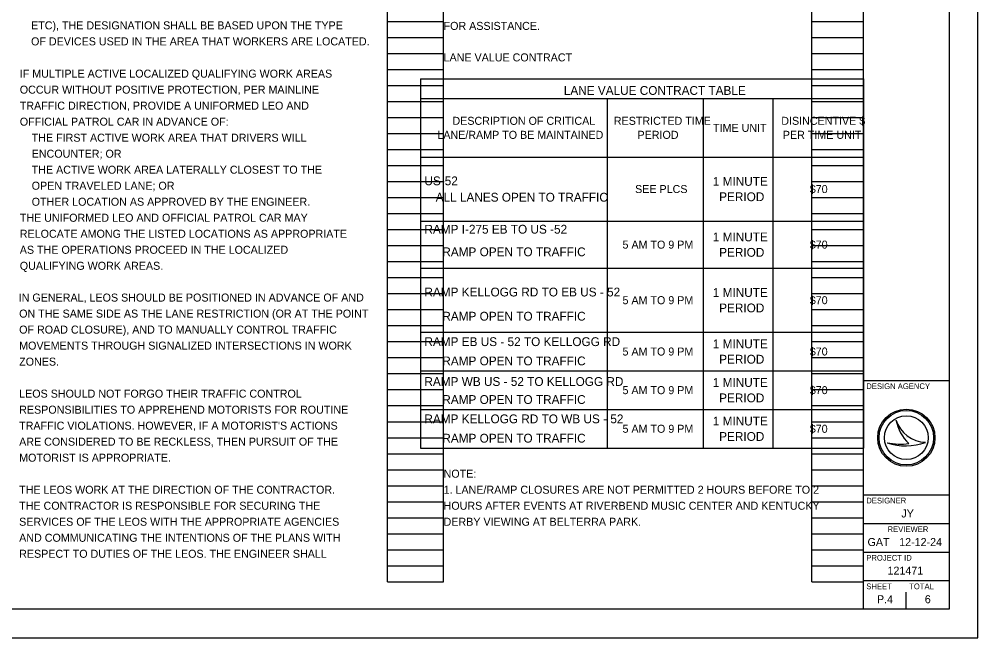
# Model space of a CAD drawing. Extents: x -40 to 107, y -47 to 37.
# Drawn here: x 17.24 to 34, y 0 to 10.82 of the extents above; entities that cross this region are included whole.
import ezdxf

# ---------------------------------------------------------------- set-up
doc = ezdxf.new("R2010")
doc.units = 0
for name, color, linetype in [('Default', 7, 'Continuous'), ('SH_Border', 7, 'Continuous'), ('SH_Cut_Line', 7, 'Continuous'), ('SH_Data', 7, 'Continuous'), ('SH_Text', 7, 'Continuous')]:
    doc.layers.add(name, color=color, linetype=linetype)

msp = doc.modelspace()

# ---------------------------------------------------------------- linework, layer by layer
at = {"layer": 'Default'}
for p, q in [((24.259, 9.775), (32, 9.775)), ((24.259, 9.775), (24.259, 3.318)), ((32, 9.775), (32, 3.318)), ((24.259, 9.429), (27.52, 9.429)), ((27.52, 9.429), (32, 9.429)), ((27.52, 9.429), (27.52, 3.318)), ((29.2, 9.429), (29.2, 3.318)), ((30.419, 9.429), (30.419, 3.318)), ((24.259, 8.408), (32, 8.408)), ((24.259, 7.288), (32, 7.288)), ((24.259, 6.464), (32, 6.464)), ((24.259, 5.344), (32, 5.344)), ((24.259, 4.669), (32, 4.669)), ((24.259, 3.994), (32, 3.994)), ((24.259, 3.318), (32, 3.318))]:
    msp.add_line(p, q, dxfattribs=at)
at = {"layer": 'SH_Border'}
for p, q in [((32, 0.5), (32, 21.5)), ((32, 4.5), (33.5, 4.5)), ((32, 2.5), (33.5, 2.5)), ((32, 2), (33.5, 2)), ((32, 1.5), (33.5, 1.5)), ((32, 1), (33.5, 1))]:
    msp.add_line(p, q, dxfattribs=at)
msp.add_lwpolyline([(1.5, 21.5), (33.5, 21.5), (33.5, 0.5), (1.5, 0.5)], close=True, dxfattribs=at)
at = {"layer": 'SH_Cut_Line'}
msp.add_lwpolyline([(0, 0), (34, 0), (34, 22), (0, 22)], close=True, dxfattribs=at)
at = {"layer": 'SH_Data'}
for p, q in [((23.68, 0.98), (23.68, 21.14)), ((24.66, 0.98), (24.66, 21.14)), ((31.1, 0.98), (31.1, 21.14)), ((32, 0.98), (32, 21.14)), ((23.68, 10.78), (24.66, 10.78)), ((31.1, 10.78), (32, 10.78)), ((23.68, 10.5), (24.66, 10.5)), ((31.1, 10.5), (32, 10.5)), ((23.68, 10.22), (24.66, 10.22)), ((31.1, 10.22), (32, 10.22)), ((23.68, 9.94), (24.66, 9.94)), ((31.1, 9.94), (32, 9.94)), ((23.68, 9.66), (24.66, 9.66)), ((31.1, 9.66), (32, 9.66)), ((23.68, 9.38), (24.66, 9.38)), ((31.1, 9.38), (32, 9.38)), ((23.68, 9.1), (24.66, 9.1)), ((31.1, 9.1), (32, 9.1)), ((23.68, 8.82), (24.66, 8.82)), ((31.1, 8.82), (32, 8.82)), ((23.68, 8.54), (24.66, 8.54)), ((31.1, 8.54), (32, 8.54)), ((23.68, 8.26), (24.66, 8.26)), ((31.1, 8.26), (32, 8.26)), ((23.68, 7.98), (24.66, 7.98)), ((31.1, 7.98), (32, 7.98)), ((23.68, 7.7), (24.66, 7.7)), ((31.1, 7.7), (32, 7.7)), ((23.68, 7.42), (24.66, 7.42)), ((31.1, 7.42), (32, 7.42)), ((23.68, 7.14), (24.66, 7.14)), ((31.1, 7.14), (32, 7.14)), ((23.68, 6.86), (24.66, 6.86)), ((31.1, 6.86), (32, 6.86)), ((23.68, 6.58), (24.66, 6.58)), ((31.1, 6.58), (32, 6.58)), ((23.68, 6.3), (24.66, 6.3)), ((31.1, 6.3), (32, 6.3)), ((23.68, 6.02), (24.66, 6.02)), ((31.1, 6.02), (32, 6.02)), ((23.68, 5.74), (24.66, 5.74)), ((31.1, 5.74), (32, 5.74)), ((23.68, 5.46), (24.66, 5.46)), ((31.1, 5.46), (32, 5.46)), ((23.68, 5.18), (24.66, 5.18)), ((31.1, 5.18), (32, 5.18)), ((23.68, 4.9), (24.66, 4.9)), ((31.1, 4.9), (32, 4.9)), ((23.68, 4.62), (24.66, 4.62)), ((31.1, 4.62), (32, 4.62)), ((23.68, 4.34), (24.66, 4.34)), ((31.1, 4.34), (32, 4.34)), ((23.68, 4.06), (24.66, 4.06)), ((31.1, 4.06), (32, 4.06)), ((23.68, 3.78), (24.66, 3.78)), ((31.1, 3.78), (32, 3.78)), ((32.567, 3.81), (32.567, 3.81)), ((23.68, 3.5), (24.66, 3.5)), ((31.1, 3.5), (32, 3.5)), ((32.417, 3.41), (32.417, 3.41)), ((32.75, 3.5), (32.75, 3.5)), ((33.087, 3.419), (33.087, 3.419)), ((23.68, 3.22), (24.66, 3.22)), ((31.1, 3.22), (32, 3.22)), ((23.68, 2.94), (24.66, 2.94)), ((31.1, 2.94), (32, 2.94)), ((23.68, 2.66), (24.66, 2.66)), ((31.1, 2.66), (32, 2.66)), ((23.68, 2.38), (24.66, 2.38)), ((31.1, 2.38), (32, 2.38)), ((23.68, 2.1), (24.66, 2.1)), ((31.1, 2.1), (32, 2.1)), ((23.68, 1.82), (24.66, 1.82)), ((31.1, 1.82), (32, 1.82)), ((23.68, 1.54), (24.66, 1.54)), ((31.1, 1.54), (32, 1.54)), ((23.68, 1.26), (24.66, 1.26)), ((31.1, 1.26), (32, 1.26)), ((23.68, 0.98), (24.66, 0.98)), ((31.1, 0.98), (32, 0.98)), ((32.375, 0.675), (32.375, 0.675)), ((32.75, 0.5), (32.75, 0.8))]:
    msp.add_line(p, q, dxfattribs=at)
for radius in [0.5, 0.477, 0.477, 0.382]:
    msp.add_circle((32.75, 3.5), radius, dxfattribs=at)
for centre, radius, start, end in [((33.116, 3.998), 0.58, 198.9257, 198.9319), ((33.347, 3.97), 0.796, 191.6379, 191.6421), ((33.116, 3.998), 0.58, 198.9319, 267.1657), ((33.347, 3.97), 0.796, 191.6421, 226.0947), ((32.739, 4.37), 1.013, 251.4576, 290.0832), ((32.648, 4.654), 1.266, 259.4964, 259.4995), ((32.739, 4.37), 1.013, 251.4527, 251.4576), ((32.648, 4.654), 1.266, 259.4995, 276.6672)]:
    msp.add_arc(centre, radius, start, end, dxfattribs=at)

# ---------------------------------------------------------------- texts
at = {"layer": 'Default'}
for s, height, p in [('LANE VALUE CONTRACT', 0.14, (24.66, 10.08)), ('LANE VALUE CONTRACT TABLE', 0.154, (26.762, 9.495)), ('DESCRIPTION OF CRITICAL ', 0.14, (24.815, 8.971)), ('RESTRICTED TIME ', 0.14, (27.637, 8.971)), ('DISINCENTIVE $ ', 0.14, (30.564, 8.971)), ('TIME UNIT', 0.14, (29.371, 8.848)), ('LANE/RAMP TO BE MAINTAINED', 0.14, (24.551, 8.726)), ('PERIOD', 0.14, (28.05, 8.726)), ('PER TIME UNIT', 0.14, (30.591, 8.726)), ('US-52', 0.154, (24.325, 7.914)), ('1 MINUTE ', 0.154, (29.367, 7.905)), ('SEE PLCS', 0.14, (28.008, 7.778)), ('$70', 0.14, (31.062, 7.778)), ('ALL LANES OPEN TO TRAFFIC', 0.154, (24.522, 7.628)), ('PERIOD', 0.154, (29.478, 7.636)), ('RAMP I-275 EB TO US -52', 0.154, (24.325, 7.068)), ('1 MINUTE ', 0.154, (29.367, 6.934)), ('5 AM TO 9 PM', 0.14, (27.788, 6.806)), ('$70', 0.14, (31.062, 6.806)), ('RAMP OPEN TO TRAFFIC', 0.154, (24.638, 6.673)), ('PERIOD', 0.154, (29.478, 6.664)), ('RAMP KELLOGG RD TO EB US - 52', 0.154, (24.325, 5.97)), ('1 MINUTE ', 0.154, (29.367, 5.962)), ('5 AM TO 9 PM', 0.14, (27.788, 5.834)), ('$70', 0.14, (31.062, 5.834)), ('RAMP OPEN TO TRAFFIC', 0.154, (24.638, 5.547)), ('PERIOD', 0.154, (29.478, 5.692)), ('RAMP EB US - 52 TO KELLOGG RD', 0.154, (24.325, 5.102)), ('1 MINUTE ', 0.154, (29.367, 5.064)), ('5 AM TO 9 PM', 0.14, (27.788, 4.937)), ('$70', 0.14, (31.062, 4.937)), ('RAMP OPEN TO TRAFFIC', 0.154, (24.638, 4.765)), ('PERIOD', 0.154, (29.478, 4.795)), ('RAMP WB US - 52 TO KELLOGG RD', 0.154, (24.325, 4.405)), ('1 MINUTE ', 0.154, (29.367, 4.389)), ('5 AM TO 9 PM', 0.14, (27.788, 4.261)), ('$70', 0.14, (31.062, 4.261)), ('RAMP OPEN TO TRAFFIC', 0.154, (24.638, 4.09)), ('PERIOD', 0.154, (29.478, 4.119)), ('RAMP KELLOGG RD TO WB US - 52', 0.154, (24.325, 3.752)), ('1 MINUTE ', 0.154, (29.367, 3.714)), ('5 AM TO 9 PM', 0.14, (27.788, 3.586)), ('$70', 0.14, (31.062, 3.586)), ('RAMP OPEN TO TRAFFIC', 0.154, (24.638, 3.414)), ('PERIOD', 0.154, (29.478, 3.444)), ('NOTE:', 0.14, (24.66, 2.8)), ('1. LANE/RAMP CLOSURES ARE NOT PERMITTED 2 HOURS BEFORE TO 2', 0.14, (24.66, 2.52)), ('HOURS AFTER EVENTS AT RIVERBEND MUSIC CENTER AND KENTUCKY', 0.14, (24.66, 2.24)), ('DERBY VIEWING AT BELTERRA PARK.', 0.14, (24.66, 1.96))]:
    msp.add_text(s, height=height, dxfattribs=at).set_placement(p)
at = {"layer": 'SH_Data'}
for s, height, p in [('DESIGN AGENCY', 0.1, (32.05, 4.35)), ('DESIGNER', 0.1, (32.05, 2.35)), ('JY', 0.14, (32.663, 2.105)), ('REVIEWER', 0.1, (32.422, 1.85)), ('GAT', 0.14, (32.072, 1.605)), ('12-12-24', 0.14, (32.625, 1.605)), ('PROJECT ID', 0.1, (32.05, 1.35)), ('121471', 0.14, (32.421, 1.105)), ('SHEET', 0.1, (32.05, 0.85)), ('TOTAL', 0.1, (32.8, 0.85)), ('P.4', 0.14, (32.237, 0.605)), ('6', 0.14, (33.073, 0.605))]:
    msp.add_text(s, height=height, dxfattribs=at).set_placement(p)
at = {"layer": 'SH_Text'}
for s, p in [('    ETC), THE DESIGNATION SHALL BE BASED UPON THE TYPE', (17.24, 10.64)), ('FOR ASSISTANCE.', (24.66, 10.631)), ('    OF DEVICES USED IN THE AREA THAT WORKERS ARE LOCATED.', (17.24, 10.36)), ('    IF MULTIPLE ACTIVE LOCALIZED QUALIFYING WORK AREAS', (17.043, 9.796)), ('    OCCUR WITHOUT POSITIVE PROTECTION, PER MAINLINE', (17.043, 9.516)), ('    TRAFFIC DIRECTION, PROVIDE A UNIFORMED LEO AND', (17.043, 9.236)), ('    OFFICIAL PATROL CAR IN ADVANCE OF:', (17.043, 8.956)), ('        THE FIRST ACTIVE WORK AREA THAT DRIVERS WILL', (17.043, 8.676)), ('        ENCOUNTER; OR', (17.043, 8.396)), ('        THE ACTIVE WORK AREA LATERALLY CLOSEST TO THE', (17.043, 8.116)), ('        OPEN TRAVELED LANE; OR', (17.043, 7.836)), ('        OTHER LOCATION AS APPROVED BY THE ENGINEER.', (17.043, 7.556)), ('    THE UNIFORMED LEO AND OFFICIAL PATROL CAR MAY', (17.043, 7.276)), ('    RELOCATE AMONG THE LISTED LOCATIONS AS APPROPRIATE', (17.043, 6.996)), ('    AS THE OPERATIONS PROCEED IN THE LOCALIZED', (17.043, 6.716)), ('    QUALIFYING WORK AREAS.', (17.043, 6.436)), ('IN GENERAL, LEOS SHOULD BE POSITIONED IN ADVANCE OF AND', (17.232, 5.88)), ('ON THE SAME SIDE AS THE LANE RESTRICTION (OR AT THE POINT', (17.24, 5.6)), ('OF ROAD CLOSURE), AND TO MANUALLY CONTROL TRAFFIC', (17.24, 5.32)), ('MOVEMENTS THROUGH SIGNALIZED INTERSECTIONS IN WORK', (17.24, 5.04)), ('ZONES.', (17.24, 4.76)), ('LEOS SHOULD NOT FORGO THEIR TRAFFIC CONTROL', (17.24, 4.2)), ('RESPONSIBILITIES TO APPREHEND MOTORISTS FOR ROUTINE', (17.24, 3.92)), ("TRAFFIC VIOLATIONS. HOWEVER, IF A MOTORIST'S ACTIONS", (17.24, 3.64)), ('ARE CONSIDERED TO BE RECKLESS, THEN PURSUIT OF THE', (17.24, 3.36)), ('MOTORIST IS APPROPRIATE.', (17.24, 3.08)), ('THE LEOS WORK AT THE DIRECTION OF THE CONTRACTOR.', (17.24, 2.52)), ('THE CONTRACTOR IS RESPONSIBLE FOR SECURING THE', (17.24, 2.24)), ('SERVICES OF THE LEOS WITH THE APPROPRIATE AGENCIES', (17.24, 1.96)), ('AND COMMUNICATING THE INTENTIONS OF THE PLANS WITH', (17.24, 1.68)), ('RESPECT TO DUTIES OF THE LEOS. THE ENGINEER SHALL', (17.24, 1.4))]:
    msp.add_text(s, height=0.14, dxfattribs=at).set_placement(p)

doc.saveas('drawing.dxf')
